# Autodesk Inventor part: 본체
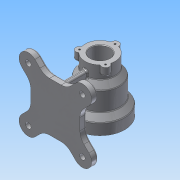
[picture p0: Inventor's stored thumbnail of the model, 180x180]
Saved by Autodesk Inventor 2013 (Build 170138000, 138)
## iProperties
Created: 2017-03
Part Number: 본체
Material: 알루미늄 6061
Document SubType Name: Modeling
Designer: Administrator
Density: 2.71 g/cm^3
Mass: 1008.36 g
Surface Area: 841.605 cm^2
Volume: 372.09 cm^3
Author: Administrator
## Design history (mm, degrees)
sketch "스케치1"
  geometry: L1 (0, 50)-(0, -50); L2 (0, -50)-(45, -50); L3 (45, -50)-(45, -30); L4 (45, -30)-(36, -19); L5 (36, -19)-(36, 15); L6 (36, 15)-(27.5, 27); L7 (27.5, 27)-(27.5, 50); L8 (27.5, 50)-(0, 50); 1 further point
  constraints: 16 end point, 3 parallel, 2 perpendicular, 1 midpoint, 1 vertical
  dimensions: "d0" = 100 distance of L1.start L1.end; "d2" = 90 diameter of L3 L1; "d3" = 72 diameter of L5 L1; "d4" = 55 diameter of L7 L1; "d5" = 65 distance from line of L5.end L2; "d6" = 20 distance of L2.end L3.end; "d7" = 31 vertical distance of L4.end L2.end; "d8" = 23 distance from line of L8 L6.end; "d9" = 50 distance from line of point (0, 0) L8
revolve "회전1" sketch "스케치1" stored, may be unused: angle "d10" = 90 deg
fillet "모깎기1" dims "d11" = 3
node "작업 평면1"
sketch "스케치2"
  geometry: L1 (-45, 45)-(45, 45); L2 (45, 45)-(45, -45); L3 (45, -45)-(-45, -45); L4 (-45, -45)-(-45, 45); L5 (-45, 45)-(45, -45); L6 (45, 45)-(-45, -45); L7 (49.497, 49.497)-(45, 45); L8 (20.958, 45)-(37.477, 61.518); L9 (45, 20.958)-(61.518, 37.477); A1 r 70 centre (0, 0) between (49.497, 49.497) and (36.106, 59.97); A2 r 17 centre (49.497, 49.497) between (59.97, 36.106) and (36.106, 59.97); 3 further points
  constraints: 18 end point, 7 point on circle, 5 midpoint, 4 parallel, 2 centre point, 2 coincident, 2 point on line, 1 collinear, 1 horizontal, 1 perpendicular
  dimensions: "d13" = 90 distance of L1.end L2.end; "d15" = 90 distance of L2.end L3.end; "d16" = 140 diameter of A1; "d17" = 34 diameter of A2; "d21" = 34 distance between parallel lines of L9 L8; "d22" = 17 distance between parallel lines of L7 L8
extrude "돌출1" join sketch "스케치2" distance "d23" = 12; taper "d24" = 0 deg
extrude "돌출2" join sketch "스케치2" distance "d25" = 12; taper "d26" = 0 deg
sketch "스케치3"
  geometry: C1 r 5 at (-49.497, -49.497); A1 r 17 centre (-49.497, -49.497) between (-61.518, -37.477) and (-37.477, -61.518) reference; 1 further point
  constraints: 1 centre point, 1 coincident
  dimensions: "d31" = 10 diameter of C1
extrude "돌출3" cut sketch "스케치3" distance "d33" = 12; taper "d34" = 0 deg
fillet "모깎기2" dims "d30" = 25
fillet "모깎기3" dims "d35" = 3
sketch "스케치4"
  geometry: L1 (4, -37)-(-4, -37); L2 (-4, -37)-(-4, 37); L3 (-4, 37)-(4, 37); L4 (4, 37)-(4, -37); L5 (4, -37)-(-4, 37); L6 (-4, -37)-(4, 37); 3 further points
  constraints: 12 end point, 3 midpoint, 2 parallel, 1 coincident, 1 horizontal, 1 perpendicular
  dimensions: "d36" = 37 distance from line of L3 point (0, 0); "d37" = 8 distance of L2.end L3.end
extrude "돌출4" join sketch "스케치4" stored distance "d38" = 12; taper "d39" = 0 deg
sketch "스케치5"
  geometry: L1 (-18.265, -31.807)-(-25, -70); L2 (-39.598, -70)-(-30.402, -70) reference; A1 r 36.678 centre (0, 0) between (4, -36.459) and (-4, -36.459) reference; 1 further point
  constraints: 2 end point, 1 point on circle, 1 point on line
  dimensions: "d40" = 25 horizontal distance of point (0, 0) L1.end; "d41" = 100 deg angle of L2 L1
feature "리브1" sketch "스케치5" dims "d42" = 1, "d43" = 8, "d44" = 0, "d45" = 0, "d46" = 1, "d47" = 1
fillet "모깎기4" dims "d48" = 3
fillet "모깎기5" dims "d49" = 3
sketch "스케치6"
  geometry: L1 (35, -50)-(35, -27); L2 (35, -27)-(26, -27); L3 (26, -27)-(26, 20); L4 (26, 20)-(17.5, 20); L5 (17.5, 20)-(17.5, 50); L6 (-45, -50)-(45, -50) reference; L7 (-27.5, 50)-(27.5, 50) reference; L8 (0, -50)-(0, 50); L9 (35, -50)-(0, -50); L10 (17.5, 50)-(0, 50); 1 further point
  constraints: 16 end point, 3 parallel, 2 midpoint, 2 point on line, 1 collinear, 1 horizontal, 1 perpendicular, 1 vertical
  dimensions: "d50" = 23 distance of L1.start L1.end; "d52" = 47 distance of L2.end L3.end; "d53" = 70 diameter of L1 L8; "d54" = 52 diameter of L3 L8; "d55" = 35 diameter of L5 L8
revolve "회전2" sketch "스케치6" stored, may be unused: angle "d56" = 90 deg
chamfer "모따기1" distance "d57" = 1; stored, may be unused: second distance "d58" = 2, angle "d59" = 45 deg
fillet "모깎기6" dims "d60" = 3
sketch "스케치7" dims "d61" = 80
  geometry: C1 r 45 at (0, 0) reference; 2 further points
  constraints: 2 vertical alignment, 1 coincident, 2 other
hole "구멍1" sketch "스케치7" at (0, 40) diameter "d63" = 3.242; stored, may be unused: countersink angle "d67" = 90 deg, drill point angle "d69" = 118 deg; dims "d64" = 9, "d65" = 4, "d66" = 2, "d68" = 11
sketch "스케치8"
  geometry: C1 r 7 at (0, 27.5); 1 further point
  constraints: 2 vertical alignment, 1 centre point, 1 other
  dimensions: "d73" = 14 diameter of C1
extrude "돌출5" join sketch "스케치8" distance "d75" = 15; taper "d76" = 0 deg
fillet "모깎기7" dims "d77" = 3, "d108" = 1
hole "구멍2" diameter "d80" = 3.242; stored, may be unused: countersink angle "d84" = 90 deg, drill point angle "d86" = 118 deg; dims "d78" = 10, "d79" = 10, "d81" = 9, "d82" = 4, "d83" = 2, "d85" = 11
node "작업 평면2"
sketch "스케치9"
  geometry: C1 r 5 at (0, 0); 1 further point
  constraints: 1 centre point, 1 coincident
  dimensions: "d91" = 10 diameter of C1
extrude "돌출6" join sketch "스케치9" stored distance "d93" = 15; taper "d94" = 0 deg
fillet "모깎기8" dims "d95" = 3
hole "구멍3" diameter "d98" = 4.134; stored, may be unused: countersink angle "d102" = 90 deg, drill point angle "d104" = 118 deg; dims "d96" = 10, "d97" = 10, "d99" = 9, "d100" = 4, "d101" = 2, "d103" = 34
sketch "스케치10"
  geometry: 2 further points
  constraints: 1 horizontal alignment, 1 other
  dimensions: "d105" = 35 distance of point (0, 0) point (-35, 0)
feature "엠보싱1" sketch "스케치10" dims "d13" = 90, "d15" = 90, "d16" = 140, "d17" = 34, "d21" = 34, "d22" = 17, "d106" = 0.5, "d107" = 0
node "솔리드1"
pattern_circular "원형 패턴1" dims angle "d28" = 360 deg
mirror "대칭1"
pattern_circular "원형 패턴2" dims angle "d71" = 360 deg
pattern_circular "원형 패턴3" dims "d88" = 360 deg
other parameters: "d12" = -82
